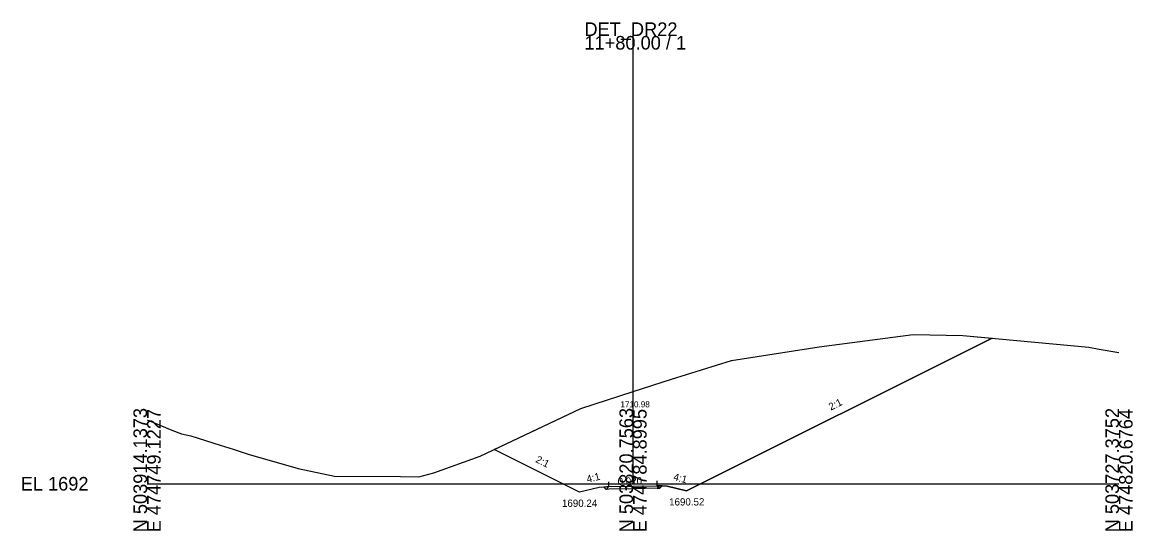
# Model space of a CAD drawing. Extents: x -26 to 1203, y -10 to 9633.
# Drawn here: x -25.7 to 202.8, y 4490.3 to 4595.1 of the extents above; entities that cross this region are included whole.
import ezdxf

# ---------------------------------------------------------------- set-up
doc = ezdxf.new("R2010")
doc.units = 0
for name, color, linetype in [('Exist Cross Section Cell', 7, 'Continuous'), ('Exist XS Center Line Elevation Label', 7, 'Continuous'), ('Exist XS Ground Line', 7, 'Continuous'), ('Prop XS Ditch Slope Text', 7, 'Continuous'), ('Prop XS Ditch Standard Text', 7, 'Continuous'), ('Prop XS Earthwork Shape', 7, 'Continuous'), ('Prop XS EOT Tick Mark', 7, 'Continuous'), ('Prop XS Finish Grade', 7, 'Continuous'), ('Prop XS Finish Grade Earthwork', 7, 'Continuous'), ('Prop XS Finish Grade Pavement', 7, 'Continuous'), ('Prop XS Pvmt Edge Slope', 7, 'Continuous'), ('Prop XS SE Text', 7, 'Continuous'), ('Prop XS Shoulder Borrow Shape', 7, 'Continuous'), ('Prop XS Side Slope Text', 7, 'Continuous'), ('Prop XS Subgrade Earthwork', 7, 'Continuous')]:
    doc.layers.add(name, color=color, linetype=linetype)

msp = doc.modelspace()

# ---------------------------------------------------------------- linework, layer by layer
at = {"layer": 'Exist Cross Section Cell'}
for p, q in [((100, 4500), (100, 4592.22)), ((0, 4500), (100, 4500)), ((100, 4500), (200, 4500))]:
    msp.add_line(p, q, dxfattribs=at)
at = {"layer": 'Exist XS Ground Line'}
msp.add_lwpolyline([(0, 4513.17), (5.08, 4511.01), (7.06, 4510.31), (9, 4509.86), (15.04, 4507.92), (17.69, 4507.14), (20.81, 4506.09), (31.08, 4503.11), (38.58, 4501.57), (52.18, 4501.46), (55.95, 4501.42), (59.02, 4502.26), (68.55, 4505.67), (89.26, 4515.5), (100, 4518.98), (107.95, 4521.55), (120.25, 4525.36), (138.33, 4528.21), (157.63, 4530.74), (167.84, 4530.53), (193.78, 4528.14), (195.89, 4527.73), (200, 4527.03)], dxfattribs=at)
at = {"layer": 'Prop XS Earthwork Shape'}
msp.add_lwpolyline([(93.98, 4499.31), (93, 4499.24), (89, 4498.24), (71.41, 4507.03), (89.26, 4515.5), (100, 4518.98), (107.95, 4521.55), (120.25, 4525.36), (138.33, 4528.21), (157.63, 4530.74), (167.84, 4530.53), (173.91, 4529.97), (111, 4498.52), (107, 4499.52), (106.02, 4499.56), (105.53, 4499.07), (105, 4499.06), (100, 4498.96), (95, 4498.86), (94.45, 4498.84)], close=True, dxfattribs=at)
at = {"layer": 'Prop XS EOT Tick Mark'}
for p, q in [((95, 4499.4), (95, 4500.4)), ((105, 4499.6), (105, 4500.6))]:
    msp.add_line(p, q, dxfattribs=at)
at = {"layer": 'Prop XS Finish Grade'}
for p, q in [((95, 4499.4), (93.98, 4499.31)), ((105, 4499.6), (106.02, 4499.56))]:
    msp.add_line(p, q, dxfattribs=at)
at = {"layer": 'Prop XS Finish Grade Earthwork'}
for p, q in [((111, 4498.52), (173.91, 4529.97)), ((89, 4498.24), (71.41, 4507.03)), ((93, 4499.24), (89, 4498.24)), ((93.98, 4499.31), (93, 4499.24)), ((106.02, 4499.56), (107, 4499.52)), ((107, 4499.52), (111, 4498.52))]:
    msp.add_line(p, q, dxfattribs=at)
at = {"layer": 'Prop XS Finish Grade Pavement'}
for p, q in [((95, 4499.4), (100, 4499.5)), ((100, 4499.5), (105, 4499.6))]:
    msp.add_line(p, q, dxfattribs=at)
at = {"layer": 'Prop XS Pvmt Edge Slope'}
for p, q in [((95, 4499.4), (94.45, 4498.84)), ((105, 4499.6), (105.53, 4499.07))]:
    msp.add_line(p, q, dxfattribs=at)
at = {"layer": 'Prop XS Shoulder Borrow Shape'}
for points in [[(95, 4499.4), (94.45, 4498.84), (93.98, 4499.31)], [(105.53, 4499.07), (106.02, 4499.56), (105, 4499.6)]]:
    msp.add_lwpolyline(points, close=True, dxfattribs=at)
at = {"layer": 'Prop XS Subgrade Earthwork'}
for p, q in [((94.45, 4498.84), (93.98, 4499.31)), ((95, 4498.86), (94.45, 4498.84)), ((100, 4498.96), (95, 4498.86)), ((105, 4499.06), (100, 4498.96)), ((105, 4499.06), (105.53, 4499.07)), ((105.53, 4499.07), (106.02, 4499.56))]:
    msp.add_line(p, q, dxfattribs=at)

# ---------------------------------------------------------------- texts
at = {"layer": 'Exist Cross Section Cell'}
for s, p in [('DET_DR22', (90, 4592.22)), ('11+80.00 / 1', (90, 4589.42)), ('EL 1692', (-26, 4498.6))]:
    msp.add_text(s, height=2.8, dxfattribs=at).set_placement(p)
for s, p in [('N 503914.1373', (0, 4490)), ('E 474749.1227', (2.8, 4490)), ('N 503820.7563', (100, 4490)), ('E 474784.8995', (102.8, 4490)), ('N 503727.3752', (200, 4490)), ('E 474820.6764', (202.8, 4490))]:
    msp.add_text(s, height=2.8, rotation=90, dxfattribs=at).set_placement(p)
at = {"layer": 'Exist XS Center Line Elevation Label'}
msp.add_text('1710.98', height=1.25, dxfattribs=at).set_placement((97.41, 4515.73))
at = {"layer": 'Prop XS Ditch Slope Text'}
for rotation, p in [(14.0362, (90.64, 4500.19)), (345.9638, (108.21, 4500.76))]:
    msp.add_text('4:1', height=1.5, rotation=rotation, dxfattribs=at).set_placement(p)
at = {"layer": 'Prop XS Ditch Standard Text'}
for s, p in [('1690.24', (85.38, 4495.24)), ('1690.52', (107.43, 4495.52))]:
    msp.add_text(s, height=1.5, dxfattribs=at).set_placement(p)
at = {"layer": 'Prop XS SE Text'}
msp.add_text('0.020', height=1.5, rotation=1.1458, dxfattribs=at).set_placement((96.85, 4499.76))
at = {"layer": 'Prop XS Side Slope Text'}
for rotation, p in [(26.5651, (140.72, 4515.05)), (333.4349, (79.81, 4504.51))]:
    msp.add_text('2:1', height=1.5, rotation=rotation, dxfattribs=at).set_placement(p)

doc.saveas('drawing.dxf')
